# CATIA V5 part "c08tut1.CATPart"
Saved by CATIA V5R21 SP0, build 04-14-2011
Part number: Part1
Bounding box of the stored display mesh (mm): x -175 to 175, y -250 to 250, z -8 to 100
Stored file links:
  D:\CATIA V5R21 E-RESOURCES\CATIA-V5R21\catia-v5r21-prt\c08-catia-v5r20-prt\c08-catia-v5r21-tut01.CATPart
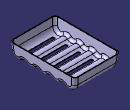
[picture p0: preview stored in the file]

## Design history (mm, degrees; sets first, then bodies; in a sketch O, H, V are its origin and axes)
Body1 (main body)
  Sketch1 on yz-plane, origin (0, 0, 0), H (0, 1, 0), V (0, 0, 1)
    line L1 (250, 100) -> (250, 0)
    line L2 (250, 0) -> (-250, 0)
    line L3 (-250, 0) -> (-250, 100)
    line L4 (-250, 100) -> (250, 100)
    length L1 = 100
    length L4 = 500
    distance V L1 = 250
    vertical: L1 V, L3 V
    horizontal: L2 H, L4 H
    coincidence: H L2
  Pad1: profile Sketch1, direction (1, 0, 0), length 175, mirrored extent
  Draft1: Angle 5, Neutral face of Pad1 from Sketch1.L4, PullDir face of Pad1 from Sketch1.L4
  Sketch2 on yz-plane, origin (0, 0, 0), H (0, 1, 0), V (0, 0, 1)
    arc A1 centre (-195.4346, 50) radius 50 from (-245.2443, 45.6422) to (-162.8621, 12.0654) ccw
    reference projected line E1 (-236.9099, -49.6202) -> (-245.6588, 50.3798) from edge [end face of Pad1 | face of Pad1 from Sketch1.L3]
    reference projected line E2 (241.2511, 0) -> (-241.2511, 0) from edge [end face of Pad1 | face of Pad1 from Sketch1.L2]
    arc A2 centre (195.4346, 50) radius 50 from (162.8621, 12.0654) to (245.2443, 45.6422) ccw
    reference projected line E3 (241.2511, 0) -> (-241.2511, 0) from edge [end face of Pad1 | face of Pad1 from Sketch1.L2]
    reference projected line E4 (245.6588, 50.3798) -> (236.9099, -49.6202) from edge [end face of Pad1 | face of Pad1 from Sketch1.L1]
    arc A3 centre (-146.5759, -6.902) radius 25 from (-162.8621, 12.0654) to (-130.2897, 12.0654) cw
    arc A4 centre (-48.8586, -6.902) radius 25 from (-65.1449, 12.0654) to (-32.5724, 12.0654) cw
    point P9 (-48.8586, -6.902)
    arc A5 centre (48.8586, -6.902) radius 25 from (32.5724, 12.0654) to (65.1449, 12.0654) cw
    point P12 (48.8586, -6.902)
    arc A6 centre (146.5759, -6.902) radius 25 from (130.2897, 12.0654) to (162.8621, 12.0654) cw
    construction line L1 (-146.5759, -6.902) -> (146.5759, -6.902)
    point P18 (245.2443, 45.6422)
    arc A7 centre (97.7173, 50) radius 50 from (65.1449, 12.0654) to (130.2897, 12.0654) ccw
    arc A8 centre (0, 50) radius 50 from (-32.5724, 12.0654) to (32.5724, 12.0654) ccw
    point P19 (-245.2443, 45.6422)
    arc A9 centre (-97.7173, 50) radius 50 from (-130.2897, 12.0654) to (-65.1449, 12.0654) ccw
    reference projected line E5 (245.6588, 50.3798) -> (236.9099, -49.6202) from edge [end face of Pad1 | face of Pad1 from Sketch1.L1]
    reference projected line E6 (-236.9099, -49.6202) -> (-245.6588, 50.3798) from edge [end face of Pad1 | face of Pad1 from Sketch1.L3]
    reference projected line E7 (241.2511, 0) -> (-241.2511, 0) from edge [end face of Pad1 | face of Pad1 from Sketch1.L2]
    reference projected line E8 (241.2511, 0) -> (-241.2511, 0) from edge [end face of Pad1 | face of Pad1 from Sketch1.L2]
    reference projected line E9 (241.2511, 0) -> (-241.2511, 0) from edge [end face of Pad1 | face of Pad1 from Sketch1.L2]
    radius A3 = 25
    radius A4 = 25
    radius A5 = 25
    radius A6 = 25
    radius A9 = 50
    radius A8 = 50
    radius A7 = 50
    radius A1 = 50
    radius A2 = 50
    tangency: A1 E1, A1 E2, A2 E3, A2 E4, A3 A1, A6 A2, A3 A9, A4 A8, A4 A9, A8 A5, A5 A7, A7 A6, A9 E7, A7 E8, A8 E9
    coincidence: L1 P12, P9 L1, P18 E5, P19 E6
    horizontal: L1 H
  Pocket1: profile Sketch2, direction (-1, 0, 0), through (limit type 3), opposite side through (limit type 3)
  Fillet1: radius 25, on edge [end face of Pad1 | face of Pocket1]; edge [face of Pocket1 | start face of Pad1]
  Shell1: ExtOffset 0, Face face of Pad1 from Sketch1.L4, IntOffset 5
  Sketch3 on xy-plane, origin (0, 0, 0), H (1, 0, 0), V (0, 1, 0)
    construction line L1 (-105, 195.4346) -> (105, 195.4346)
    point P1 (-105, 195.4346)
    line L2 (-105, 207.4346) -> (105, 207.4346)
    line L3 (105, 183.4346) -> (-105, 183.4346)
    arc A1 centre (105, 195.4346) radius 12 from (105, 207.4346) to (105, 183.4346) cw
    arc A2 centre (-105, 195.4346) radius 12 from (-105, 183.4346) to (-105, 207.4346) cw
    reference projected line E1 through (0, 195.4346) direction (1, 0) from axis of face of Shell1
    length L1 = 210
    distance V P1 = 105
    distance L3 L2 = 24
    horizontal: L1 H
    tangency: A1 L2, A2 L2, A1 L3, A2 L3
    coincidence: E1 L1
  Pocket2: profile Sketch3, direction (0, 0, 1), through (limit type 6)
  RectPattern1: of Pocket2, direction 1 instances 5, spacing 97.717, along edge [face of Shell1 | face of Pad1 from Sketch1.L4]
  Sketch4 on xy-plane, origin (0, 0, 0), H (1, 0, 0), V (0, 1, 0)
    circle A1 centre (-135, -195.4346) radius 10
    point P1 (-135, -195.4346)
    reference projected line E1 through (0, -195.4346) direction (1, 0) from axis of face of Shell1
    reference projected line E2 (-175, 250) -> (-175, -250) from edge [start face of Pad1 | face of Pad1 from Sketch1.L4]
    radius A1 = 10
    distance P1 E2 = 40
    coincidence: E1 P1
  Pad2: profile Sketch4, direction (0, 0, 1), up to the existing solid (limit type 2), opposite side length 8
  RectPattern2: of Pad2, direction 1 instances 2, spacing 390.868, along edge [start face of Pad1 | face of Pad1 from Sketch1.L4] reversed, direction 2 instances 2, spacing 270, along edge [face of Pad1 from Sketch1.L3 | face of Pad1 from Sketch1.L4]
